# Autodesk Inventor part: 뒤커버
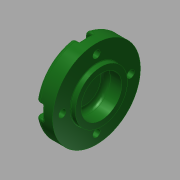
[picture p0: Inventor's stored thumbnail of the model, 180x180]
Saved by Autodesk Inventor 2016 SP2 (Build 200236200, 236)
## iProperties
Created: 2015-11
Part Number: 뒤커버
Material: 알루미늄 6061
Document SubType Name: Modeling
Designer: mduedu
Density: 1 g/cm^3
Appearance: 매끄러움 - 짙은 산림 녹색
Author: mduedu
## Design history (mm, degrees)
sketch "스케치1"
  geometry: L1 (-7, 0)-(7, 0); L2 (-7, 0)-(-7, 27); L3 (-7, 27)-(4, 27); L4 (4, 27)-(4, 16); L5 (4, 16)-(7, 16); L6 (7, 16)-(7, 0); 2 further points
  constraints: 12 end point, 3 perpendicular, 2 parallel, 1 coincident, 1 horizontal, 1 midpoint
  dimensions: "d0" = 14 distance of L1.start L1.end; "d1" = 54 diameter of L3 L1; "d2" = 3 distance of L4.end L5.end; "d3" = 32 diameter of L5 L1
revolve "회전1" sketch "스케치1" stored, may be unused: angle "d4" = 90 deg
hole "구멍1" diameter "d7" = 25; stored, may be unused: countersink angle "d11" = 90 deg, drill point angle "d13" = 0 deg; dims "d8" = 6, "d9" = 4, "d10" = 2, "d12" = 10, "d66" = 10, "d67" = 10
fillet "모깎기2" dims "d36" = 3
fillet "모깎기3" dims "d37" = 3
fillet "모깎기4" dims "d38" = 0.3
sketch "스케치3" dims "d61" = 42
  geometry: C1 r 27 at (0, 0) reference; 2 further points
  constraints: 2 vertical alignment, 1 coincident, 2 other
hole "구멍4" sketch "스케치3" at (0, 21) diameter "d44" = 4.5; stored, may be unused: countersink angle "d48" = 90 deg, drill point angle "d50" = 0 deg; dims "d45" = 6, "d46" = 8, "d47" = 4.6, "d49" = 8
sketch "스케치4"
  geometry: L1 (-4, 5.702)-(-4, 0); L2 (4, 5.702)-(4, 0); A1 r 27 centre (0, -21) between (-4, 5.702) and (4, 5.702) reference; A2 r 4 centre (0, 0) between (-2.824, 2.833) and (2.824, 2.833) reference
  constraints: 4 end point, 4 point on circle, 2 tangent, 2 vertical
extrude "돌출1" cut sketch "스케치4" stored distance "d51" = 0; taper "d52" = 0 deg
fillet "모깎기5" dims "d56" = 0.3
fillet "모깎기6" dims "d57" = 1
node "솔리드1"
pattern_circular "원형 패턴2" dims angle "d64" = 360 deg
pattern_circular "원형 패턴1" dims angle "d54" = 360 deg
